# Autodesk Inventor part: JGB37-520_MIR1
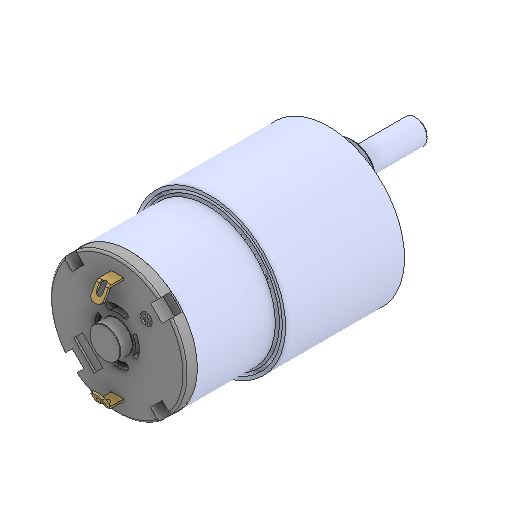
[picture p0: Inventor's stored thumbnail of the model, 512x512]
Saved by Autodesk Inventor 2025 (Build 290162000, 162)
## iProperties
Created: 2017-03
Part Number: JGB37-520_MIR1
Material: Generico
Description: STEP AP214
Document SubType Name: Modeling
Designer: R5800u
Density: 1 g/cm^3
Appearance: Default
Title: JGB37-520.STEP
Sending System: SolidWorks 2017
Preprocessor: SwSTEP 2.0
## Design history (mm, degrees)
derived "JGB37-520.ipt"
feature "Solido1::JGB37-520.ipt"
feature "Solido2::JGB37-520.ipt"
feature "Solido3::JGB37-520.ipt"
feature "Solido4::JGB37-520.ipt"
feature "Solido5::JGB37-520.ipt"
feature "Solido6::JGB37-520.ipt"
feature "Solido7::JGB37-520.ipt"
feature "Solido8::JGB37-520.ipt"
feature "Solido9::JGB37-520.ipt"
feature "Solido10::JGB37-520.ipt"
feature "Solido11::JGB37-520.ipt"
tag "Lavorazione contrassegno1"
node "Solido1"
node "Solido2"
node "Solido3"
node "Solido4"
node "Solido5"
node "Solido6"
node "Solido7"
node "Solido8"
node "Solido9"
node "Solido10"
node "Solido11"
